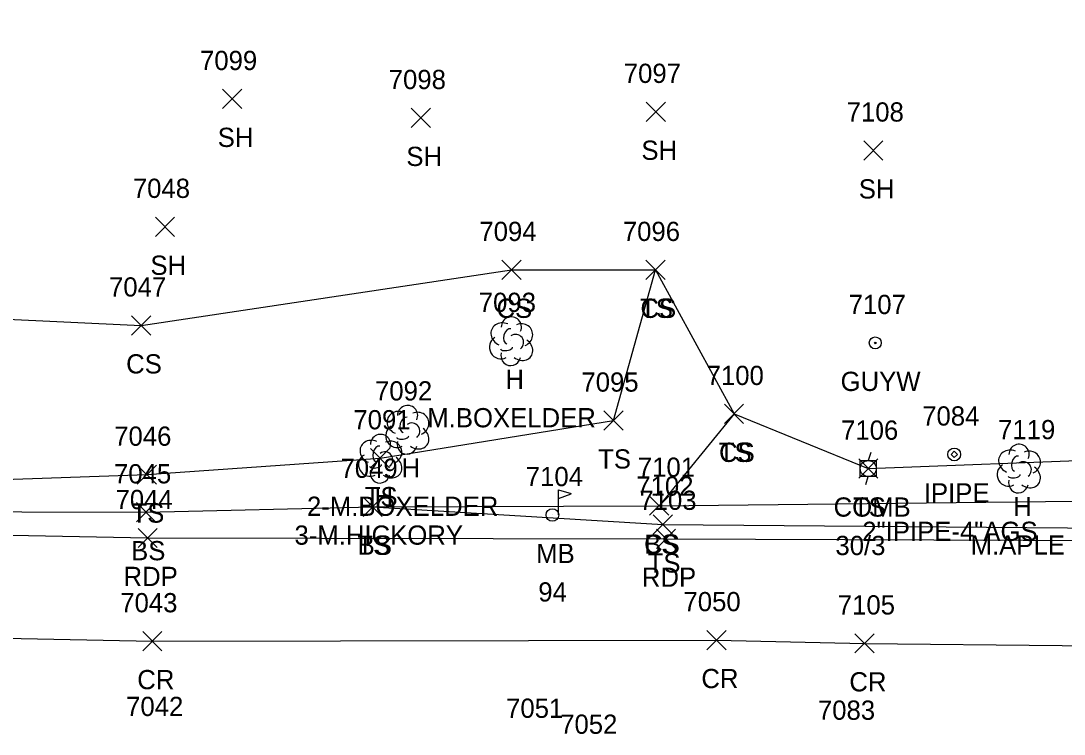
# Model space of a CAD drawing. Extents: x 1443912 to 1445411, y 621446 to 623693.
# Drawn here: x 1445132.2 to 1445240.8, y 622567.4 to 622641.6 of the extents above; entities that cross this region are included whole.
import ezdxf

# ---------------------------------------------------------------- set-up
doc = ezdxf.new("R2010")
doc.units = 0
for name, color, linetype in [('L_A', 7, 'Continuous'), ('L_C', 7, 'Continuous'), ('L_I', 7, 'Continuous'), ('L_TIC', 7, 'Continuous'), ('LELB', 7, 'Continuous'), ('LMB', 7, 'Continuous'), ('LTD', 7, 'Continuous'), ('M_A', 7, 'Continuous'), ('M_C', 7, 'Continuous'), ('M_I', 7, 'Continuous'), ('MPIP', 7, 'Continuous'), ('P_A', 7, 'Continuous'), ('P_I', 7, 'Continuous'), ('P_TIC', 7, 'Continuous'), ('PET', 7, 'Continuous'), ('PRC', 7, 'Continuous'), ('R_I', 7, 'Continuous'), ('U_A', 7, 'Continuous'), ('U_C', 7, 'Continuous'), ('U_I', 7, 'Continuous'), ('UP', 7, 'Continuous'), ('UPGW', 7, 'Continuous')]:
    doc.layers.add(name, color=color, linetype=linetype)

msp = doc.modelspace()

# ---------------------------------------------------------------- linework, layer by layer
at = {"layer": 'L_TIC'}
for points in [[(1445153.21, 622632.51), (1445155.21, 622634.51)], [(1445155.21, 622632.51), (1445153.21, 622634.51)], [(1445172.84, 622630.53), (1445174.84, 622632.53)], [(1445174.84, 622630.53), (1445172.84, 622632.53)], [(1445197.3, 622631.17), (1445199.3, 622633.17)], [(1445199.3, 622631.17), (1445197.3, 622633.17)], [(1445219.92, 622627.15), (1445221.92, 622629.15)], [(1445221.92, 622627.15), (1445219.92, 622629.15)], [(1445146.21, 622619.21), (1445148.21, 622621.21)], [(1445148.21, 622619.21), (1445146.21, 622621.21)], [(1445182.27, 622614.73), (1445184.27, 622616.73)], [(1445184.27, 622614.73), (1445182.27, 622616.73)], [(1445197.25, 622614.73), (1445199.25, 622616.73)], [(1445199.25, 622614.73), (1445197.25, 622616.73)], [(1445197.25, 622614.73), (1445199.25, 622616.73)], [(1445199.25, 622614.73), (1445197.25, 622616.73)], [(1445143.73, 622608.95), (1445145.73, 622610.95)], [(1445145.73, 622608.95), (1445143.73, 622610.95)], [(1445192.89, 622599.06), (1445194.89, 622601.06)], [(1445194.89, 622599.06), (1445192.89, 622601.06)], [(1445205.43, 622599.75), (1445207.43, 622601.75)], [(1445207.43, 622599.75), (1445205.43, 622601.75)], [(1445205.43, 622599.75), (1445207.43, 622601.75)], [(1445207.43, 622599.75), (1445205.43, 622601.75)], [(1445168.59, 622595.14), (1445170.59, 622597.14)], [(1445170.59, 622595.14), (1445168.59, 622597.14)], [(1445219.4, 622594.06), (1445221.4, 622596.06)], [(1445221.4, 622594.06), (1445219.4, 622596.06)], [(1445144.32, 622593.43), (1445146.32, 622595.43)], [(1445146.32, 622593.43), (1445144.32, 622595.43)], [(1445144.24, 622589.52), (1445146.24, 622591.52)], [(1445146.24, 622589.52), (1445144.24, 622591.52)], [(1445167.82, 622590.09), (1445169.82, 622592.09)], [(1445169.82, 622590.09), (1445167.82, 622592.09)], [(1445167.82, 622590.09), (1445169.82, 622592.09)], [(1445169.82, 622590.09), (1445167.82, 622592.09)], [(1445197.63, 622590.2), (1445199.63, 622592.2)], [(1445199.63, 622590.2), (1445197.63, 622592.2)], [(1445197.63, 622590.2), (1445199.63, 622592.2)], [(1445199.63, 622590.2), (1445197.63, 622592.2)], [(1445198.03, 622588.24), (1445200.03, 622590.24)], [(1445200.03, 622588.24), (1445198.03, 622590.24)]]:
    msp.add_lwpolyline(points, dxfattribs=at)
at = {"layer": 'LELB'}
for points in [[(1445032.66, 622641.63), (1445028.83, 622632.48), (1445026.78, 622624.17), (1445026.88, 622612.34), (1445034.97, 622594.5), (1445058.52, 622591.73), (1445106.36, 622590.63), (1445145.24, 622590.52), (1445168.82, 622591.09), (1445198.63, 622591.2), (1445245.01, 622591.72), (1445286.57, 622591.6), (1445300.71, 622591.32), (1445301.52, 622592.41)], [(1445040.06, 622622.7), (1445030.97, 622614.62), (1445043.65, 622596.97), (1445058.38, 622595.29), (1445106.61, 622593.08), (1445145.32, 622594.43), (1445169.59, 622596.14), (1445193.89, 622600.06), (1445198.25, 622615.73)], [(1445103.83, 622622.52), (1445122.01, 622611.03), (1445144.73, 622609.95), (1445183.27, 622615.73), (1445198.25, 622615.73), (1445206.43, 622600.75), (1445198.63, 622591.2)], [(1445206.43, 622600.75), (1445220.4, 622595.06), (1445245.8, 622596.04)], [(1445168.82, 622591.09), (1445199.03, 622589.24), (1445245.33, 622588.86), (1445289.62, 622589.44), (1445302.36, 622589.81), (1445302.82, 622594.71)]]:
    msp.add_lwpolyline(points, dxfattribs=at)
at = {"layer": 'LMB'}
for p, q in [((1445188.18, 622592.83), (1445189.47, 622592.45)), ((1445188.18, 622590.24), (1445188.18, 622592.83)), ((1445188.18, 622591.93), (1445189.47, 622592.44)), ((1445187.53, 622590.23), (1445187.53, 622590.23))]:
    msp.add_line(p, q, dxfattribs=at)
msp.add_circle((1445187.53, 622590.23), 0.656, dxfattribs=at)
at = {"layer": 'LTD'}
for p, q in [((1445183.21, 622608.35), (1445183.21, 622608.35)), ((1445183.21, 622608.35), (1445183.21, 622608.35)), ((1445172.41, 622599.14), (1445172.41, 622599.14)), ((1445172.41, 622599.14), (1445172.41, 622599.14)), ((1445169.59, 622596.14), (1445169.59, 622596.14)), ((1445169.59, 622596.14), (1445169.59, 622596.14)), ((1445236.04, 622595.11), (1445236.04, 622595.11)), ((1445236.04, 622595.11), (1445236.04, 622595.11))]:
    msp.add_line(p, q, dxfattribs=at)
for centre in [(1445183.26, 622609.79), (1445172.46, 622600.58), (1445169.64, 622597.57), (1445236.09, 622596.54)]:
    msp.add_arc(centre, 1.05, 335.5272, 180.9563, dxfattribs=at)
for centre, major_axis, ratio, start_param, end_param in [((1445182.42, 622609.02), (1.21, -0.51), 0.895232, 1.570796, 4.712389), ((1445184.25, 622608.94), (-1.14, -0.48), 0.949671, 1.570796, 4.712389), ((1445182.13, 622607.65), (0.58, -1.04), 0.959034, 3.141593, 6.283185), ((1445183, 622608.81), (-0.208, -0.792), 0.645439, 3.141593, 6.283185), ((1445183.71, 622608.19), (-0.5, 0.667), 0.989748, 3.141593, 6.283185), ((1445182.75, 622607.6), (-0.625, -0.083), 0.423636, 0, 3.141593), ((1445184.21, 622607.52), (-1.09, 0.79), 0.841452, 1.570796, 4.712389), ((1445183.21, 622606.85), (0.26, 1.06), 0.942809, 1.570796, 4.712389), ((1445171.62, 622599.81), (1.21, -0.51), 0.895232, 1.570796, 4.712389), ((1445173.45, 622599.73), (-1.14, -0.48), 0.949671, 1.570796, 4.712389), ((1445172.2, 622599.6), (-0.208, -0.792), 0.645439, 3.141593, 6.283185), ((1445171.33, 622598.43), (0.58, -1.04), 0.959034, 3.141593, 6.283185), ((1445172.91, 622598.97), (-0.5, 0.667), 0.989748, 3.141593, 6.283185), ((1445173.41, 622598.31), (-1.09, 0.79), 0.841452, 1.570796, 4.712389), ((1445168.8, 622596.8), (1.21, -0.51), 0.895232, 1.570796, 4.712389), ((1445170.63, 622596.72), (-1.14, -0.48), 0.949671, 1.570796, 4.712389), ((1445172.41, 622597.64), (0.26, 1.06), 0.942809, 1.570796, 4.712389), ((1445171.95, 622598.39), (-0.625, -0.083), 0.423636, 0, 3.141593), ((1445169.38, 622596.59), (-0.208, -0.792), 0.645439, 3.141593, 6.283185), ((1445170.09, 622595.97), (-0.5, 0.667), 0.989748, 3.141593, 6.283185), ((1445235.25, 622595.78), (1.21, -0.51), 0.895232, 1.570796, 4.712389), ((1445237.09, 622595.69), (-1.14, -0.48), 0.949671, 1.570796, 4.712389), ((1445168.51, 622595.43), (0.58, -1.04), 0.959034, 3.141593, 6.283185), ((1445170.59, 622595.3), (-1.09, 0.79), 0.841452, 1.570796, 4.712389), ((1445235.84, 622595.57), (-0.208, -0.792), 0.645439, 3.141593, 6.283185), ((1445236.54, 622594.94), (-0.5, 0.667), 0.989748, 3.141593, 6.283185), ((1445169.59, 622594.64), (0.26, 1.06), 0.942809, 1.570796, 4.712389), ((1445169.13, 622595.39), (-0.625, -0.083), 0.423636, 0, 3.141593), ((1445234.96, 622594.4), (0.58, -1.04), 0.959034, 3.141593, 6.283185), ((1445237.04, 622594.28), (-1.09, 0.79), 0.841452, 1.570796, 4.712389), ((1445236.04, 622593.61), (0.26, 1.06), 0.942809, 1.570796, 4.712389), ((1445235.59, 622594.36), (-0.625, -0.083), 0.423636, 0, 3.141593)]:
    msp.add_ellipse(centre, major_axis=major_axis, ratio=ratio, start_param=start_param, end_param=end_param, dxfattribs=at)
at = {"layer": 'MPIP'}
msp.add_lwpolyline([(1445229.68, 622596.53), (1445229.34, 622596.87), (1445229.01, 622596.53), (1445229.34, 622596.2)], close=True, dxfattribs=at)
msp.add_circle((1445229.34, 622596.53), 0.667, dxfattribs=at)
at = {"layer": 'P_TIC'}
for points in [[(1445144.41, 622586.84), (1445146.41, 622588.84)], [(1445146.41, 622586.84), (1445144.41, 622588.84)], [(1445198.35, 622586.76), (1445200.35, 622588.76)], [(1445200.35, 622586.76), (1445198.35, 622588.76)], [(1445144.9, 622576.11), (1445146.9, 622578.11)], [(1445146.9, 622576.11), (1445144.9, 622578.11)], [(1445203.6, 622576.22), (1445205.6, 622578.22)], [(1445205.6, 622576.22), (1445203.6, 622578.22)], [(1445219, 622575.88), (1445221, 622577.88)], [(1445221, 622575.88), (1445219, 622577.88)]]:
    msp.add_lwpolyline(points, dxfattribs=at)
at = {"layer": 'PET'}
msp.add_lwpolyline([(1444828.32, 622597.96), (1444848.5, 622596.75), (1444898.46, 622594.68), (1444911.13, 622594.32), (1444955.7, 622592.45), (1444994.25, 622591.16), (1445024.92, 622590.3), (1445058.35, 622589.13), (1445106.39, 622588.61), (1445145.41, 622587.84), (1445199.35, 622587.76), (1445245.81, 622587.57), (1445289.74, 622586.87), (1445302.68, 622587.06), (1445331.62, 622586.77), (1445351.38, 622587.4), (1445404.24, 622587)], dxfattribs=at)
at = {"layer": 'PRC'}
msp.add_lwpolyline([(1444773.11, 622588.76), (1444790.08, 622588.2), (1444813.69, 622587.07), (1444848.47, 622586.58), (1444897.84, 622583.54), (1444932.23, 622582.39), (1444986.67, 622580.69), (1445025.72, 622579.48), (1445065.67, 622578.34), (1445106.56, 622577.89), (1445145.9, 622577.11), (1445204.6, 622577.22), (1445220, 622576.88), (1445261.16, 622576.44), (1445312.23, 622575.29), (1445358.84, 622575.99), (1445405.05, 622576)], dxfattribs=at)
at = {"layer": 'UP'}
for p, q in [((1445220.65, 622596.73), (1445220.4, 622595.89)), ((1445219.57, 622594.23), (1445219.57, 622595.89)), ((1445219.57, 622595.89), (1445221.23, 622595.89)), ((1445221.23, 622595.89), (1445221.23, 622594.23)), ((1445220.4, 622595.06), (1445220.4, 622595.06)), ((1445221.23, 622594.23), (1445219.57, 622594.23)), ((1445220.15, 622593.39), (1445220.4, 622594.23))]:
    msp.add_line(p, q, dxfattribs=at)
msp.add_circle((1445220.4, 622595.06), 0.833, dxfattribs=at)
at = {"layer": 'UPGW'}
for radius in [0.625, 0.0833]:
    msp.add_circle((1445221.13, 622608.13), radius, dxfattribs=at)

# ---------------------------------------------------------------- texts
at = {"layer": 'L_A'}
for s, p in [('SH', (1445152.7, 622628.51)), ('SH', (1445172.33, 622626.53)), ('SH', (1445196.79, 622627.17)), ('SH', (1445219.41, 622623.15)), ('SH', (1445145.7, 622615.21)), ('CS', (1445181.71, 622610.73)), ('TS', (1445196.66, 622610.73)), ('CS', (1445196.69, 622610.73)), ('CS', (1445143.17, 622604.95)), ('H', (1445182.64, 622603.35)), ('TS', (1445192.29, 622595.06)), ('TS', (1445204.84, 622595.75)), ('CS', (1445204.87, 622595.75)), ('H', (1445171.84, 622594.14)), ('TS', (1445168, 622591.14)), ('H', (1445169.02, 622591.14)), ('TS', (1445143.73, 622589.43)), ('TS', (1445218.81, 622590.06)), ('H', (1445235.48, 622590.11)), ('TS', (1445167.23, 622586.09)), ('BS', (1445167.26, 622586.09)), ('CS', (1445197.07, 622586.2)), ('BS', (1445197.07, 622586.2)), ('BS', (1445143.69, 622585.52)), ('MB', (1445185.84, 622585.23)), ('TS', (1445197.44, 622584.24))]:
    msp.add_text(s, height=2, dxfattribs=at).set_placement(p)
at = {"layer": 'L_C'}
for s, p in [('M.BOXELDER', (1445174.51, 622599.35)), ('2-M.BOXELDER', (1445161.99, 622590.14)), ('3-M.HICKORY', (1445160.69, 622587.14)), ('M.APLE', (1445231.05, 622586.11)), ('94', (1445186.06, 622581.23))]:
    msp.add_text(s, height=2, dxfattribs=at).set_placement(p)
at = {"layer": 'L_I'}
for s, p in [('7099', (1445150.86, 622636.51)), ('7097', (1445194.96, 622635.17)), ('7098', (1445170.5, 622634.53)), ('7108', (1445218.15, 622631.15)), ('7048', (1445143.87, 622623.21)), ('7094', (1445179.93, 622618.73)), ('7096', (1445194.86, 622618.73)), ('7096', (1445194.86, 622618.73)), ('7047', (1445141.39, 622612.95)), ('7093', (1445179.87, 622611.35)), ('7100', (1445203.58, 622603.75)), ('7100', (1445203.58, 622603.75)), ('7095', (1445190.55, 622603.06)), ('7092', (1445169.07, 622602.14)), ('7091', (1445166.82, 622599.14)), ('7091', (1445166.82, 622599.14)), ('7106', (1445217.57, 622598.06)), ('7119', (1445233.91, 622598.11)), ('7046', (1445141.93, 622597.43)), ('7049', (1445165.48, 622594.09)), ('7049', (1445165.48, 622594.09)), ('7101', (1445196.42, 622594.2)), ('7101', (1445196.42, 622594.2)), ('7045', (1445141.91, 622593.52)), ('7104', (1445184.76, 622593.23)), ('7102', (1445196.26, 622592.24))]:
    msp.add_text(s, height=2, dxfattribs=at).set_placement(p)
at = {"layer": 'M_A'}
msp.add_text('IPIPE', height=2, dxfattribs=at).set_placement((1445226.18, 622591.53))
at = {"layer": 'M_C'}
msp.add_text('2"IPIPE-4"AGS', height=2, dxfattribs=at).set_placement((1445219.77, 622587.53))
at = {"layer": 'M_I'}
msp.add_text('7084', height=2, dxfattribs=at).set_placement((1445226.01, 622599.53))
at = {"layer": 'P_A'}
for s, p in [('RDP', (1445142.9, 622582.84)), ('RDP', (1445196.84, 622582.76)), ('CR', (1445144.33, 622572.11)), ('CR', (1445203.03, 622572.22)), ('CR', (1445218.43, 622571.88))]:
    msp.add_text(s, height=2, dxfattribs=at).set_placement(p)
at = {"layer": 'P_I'}
for s, p in [('7044', (1445142.07, 622590.84)), ('7103', (1445196.58, 622590.76)), ('7043', (1445142.56, 622580.11)), ('7050', (1445201.17, 622580.22)), ('7105', (1445217.23, 622579.88)), ('7042', (1445143.17, 622569.32)), ('7051', (1445182.71, 622569.13)), ('7083', (1445215.16, 622568.93))]:
    msp.add_text(s, height=2, dxfattribs=at).set_placement(p)
at = {"layer": 'R_I'}
for s, p in [('7051', (1445182.71, 622569.13)), ('7083', (1445215.16, 622568.93)), ('7052', (1445188.34, 622567.47))]:
    msp.add_text(s, height=2, dxfattribs=at).set_placement(p)
at = {"layer": 'U_A'}
for s, p in [('GUYW', (1445217.52, 622603.13)), ('COMB', (1445216.79, 622590.06))]:
    msp.add_text(s, height=2, dxfattribs=at).set_placement(p)
at = {"layer": 'U_C'}
msp.add_text('30/3', height=2, dxfattribs=at).set_placement((1445216.98, 622586.06))
at = {"layer": 'U_I'}
for s, p in [('7107', (1445218.36, 622611.13)), ('7106', (1445217.57, 622598.06))]:
    msp.add_text(s, height=2, dxfattribs=at).set_placement(p)

doc.saveas('drawing.dxf')
